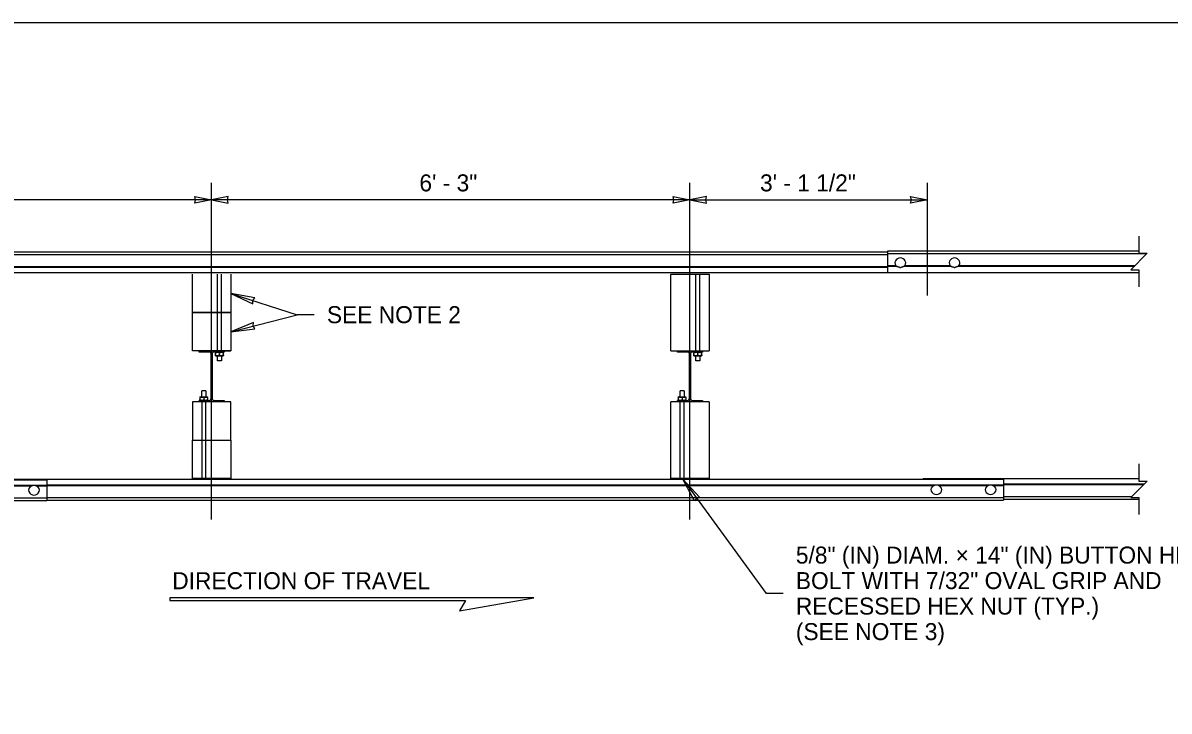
# Model space of a CAD drawing. Extents: x 99862 to 103680, y 99470 to 102076.
# Drawn here: x 101011 to 102089, y 101428 to 102076 of the extents above; entities that cross this region are included whole.
import ezdxf

# ---------------------------------------------------------------- set-up
doc = ezdxf.new("R2010")
doc.units = 0
for name, color, linetype in [('Level 1', 7, 'Continuous'), ('Level 10', 7, 'Continuous'), ('Level 14', 7, 'Continuous'), ('Level 15', 7, 'Continuous'), ('Level 2', 7, 'Continuous'), ('Level 20', 7, 'Continuous'), ('Level 27', 7, 'Continuous'), ('Level 4', 7, 'Continuous'), ('Level 7', 7, 'Continuous')]:
    doc.layers.add(name, color=color, linetype=linetype)

msp = doc.modelspace()

# ---------------------------------------------------------------- linework, layer by layer
at = {"layer": 'Level 1'}
msp.add_lwpolyline([(99862, 99999.5), (103151, 99999.5), (103151, 102075.5), (99862, 102075.5)], close=True, dxfattribs=at)
at = {"layer": 'Level 10'}
for p, q in [((101824.3, 101857.4), (100924.3, 101857.4)), ((101824.3, 101845.5), (100924.3, 101845.5)), ((100989.7, 101846.4), (101824.3, 101846.4)), ((100133.2, 101640.6), (101033.2, 101640.6)), ((101018.7, 101639.7), (100972.7, 101639.7)), ((101033.2, 101639.7), (101023.7, 101639.7)), ((101933.2, 101641.8), (102065.8, 101641.8)), ((102064.9, 101640.9), (101933.2, 101640.9)), ((100133.2, 101628.7), (101033.2, 101628.7)), ((101933.2, 101629.9), (102053.9, 101629.9))]:
    msp.add_line(p, q, dxfattribs=at)
msp.add_open_spline([(101857.7, 101646.9), (101857.7, 101646.5), (101857.7, 101646.1)], degree=2, dxfattribs=at)
at = {"layer": 'Level 14'}
for p, q in [((101188.3, 101608.2), (101188.3, 101925)), ((101638.3, 101608.2), (101638.3, 101925)), ((101861.8, 101819), (101861.8, 101925))]:
    msp.add_line(p, q, dxfattribs=at)
at = {"layer": 'Level 15'}
for p, q in [((101188.3, 101909), (100738.4, 101909)), ((101638.3, 101909), (101188.3, 101909)), ((101638.3, 101909), (101861.8, 101909)), ((101206.3, 101821), (101268.8, 101801)), ((101206.3, 101785), (101268.8, 101801)), ((101284.8, 101801), (101268.8, 101801)), ((101631.6, 101646.1), (101710, 101538.8)), ((101726, 101538.8), (101710, 101538.8))]:
    msp.add_line(p, q, dxfattribs=at)
for points in [[(101188.3, 101909), (101172.5, 101905.9), (101173.3, 101909), (101172.5, 101912.1)], [(101188.3, 101909), (101204, 101905.9), (101203.3, 101909), (101204, 101912.1)], [(101638.3, 101909), (101622.5, 101905.9), (101623.3, 101909), (101622.5, 101912.1)], [(101638.3, 101909), (101654, 101905.9), (101653.3, 101909), (101654, 101912.1)], [(101861.8, 101909), (101846, 101905.9), (101846.8, 101909), (101846, 101912.1)], [(101206.3, 101821), (101227.1, 101811.2), (101227, 101814.4), (101228.9, 101816.9)], [(101206.3, 101785), (101229.1, 101787.8), (101227.4, 101790.4), (101227.6, 101793.6)], [(101631.6, 101646.1), (101647.4, 101629.4), (101644.4, 101628.5), (101642.6, 101625.9)]]:
    msp.add_lwpolyline(points, close=True, dxfattribs=at)
for points in [[(102060.8, 101874.8), (102060.8, 101858.8), (102068.6, 101858.8), (102053.1, 101843.3), (102060.8, 101843.3), (102060.8, 101827.3)], [(102060.8, 101660.5), (102060.8, 101644.5), (102068.6, 101644.5), (102053.1, 101629.1), (102060.8, 101629.1), (102060.8, 101613.1)]]:
    msp.add_lwpolyline(points, dxfattribs=at)
at = {"layer": 'Level 2'}
for p, q in [((101170.3, 101803), (101170.3, 101839)), ((101206.3, 101839), (101206.3, 101803)), ((101620.3, 101767), (101620.3, 101839)), ((101620.3, 101839), (101656.3, 101839)), ((101656.3, 101839), (101656.3, 101767)), ((101170.3, 101767), (101170.3, 101803)), ((101170.3, 101803), (101206.3, 101803)), ((101206.3, 101803), (101170.3, 101803)), ((101206.3, 101803), (101206.3, 101767)), ((101206.3, 101767), (101170.3, 101767)), ((101201, 101767), (101206.3, 101767)), ((101620.3, 101767), (101625.5, 101767)), ((101625.5, 101767), (101651, 101767)), ((101651, 101767), (101656.3, 101767)), ((101170.3, 101719), (101170.3, 101683)), ((101206.3, 101719), (101170.3, 101719)), ((101206.3, 101683), (101206.3, 101719)), ((101620.3, 101647), (101620.3, 101719)), ((101625.5, 101719), (101620.3, 101719)), ((101651, 101719), (101625.5, 101719)), ((101656.3, 101719), (101651, 101719)), ((101656.3, 101719), (101656.3, 101647)), ((101170.3, 101683), (101206.3, 101683)), ((101170.3, 101647), (101170.3, 101683)), ((101206.3, 101683), (101206.3, 101647)), ((101206.3, 101647), (101170.3, 101647)), ((101656.3, 101647), (101620.3, 101647))]:
    msp.add_line(p, q, dxfattribs=at)
at = {"layer": 'Level 20'}
msp.add_lwpolyline([(101149, 101532.2), (101427.3, 101532.2), (101421.6, 101522.3), (101491.6, 101534.6), (101149, 101534.6)], close=True, dxfattribs=at)
at = {"layer": 'Level 27'}
for p, q in [((101824.3, 101859.8), (100924.3, 101859.8)), ((102060.8, 101860.7), (101824.3, 101860.7)), ((101824.3, 101860.7), (101824.3, 101840.4)), ((102068, 101858.3), (101824.3, 101858.3)), ((102060.8, 101840.4), (100924.3, 101840.4)), ((101824.3, 101847.3), (101832.2, 101847.3)), ((101833.4, 101846.4), (101824.3, 101846.4)), ((101884.4, 101846.4), (101839.2, 101846.4)), ((101840.3, 101847.3), (101883.2, 101847.3)), ((102056.1, 101846.4), (101890.2, 101846.4)), ((101891.3, 101847.3), (102057.1, 101847.3)), ((100133.2, 101645.6), (101033.2, 101645.6)), ((100958.2, 101646.1), (101933.2, 101646.1)), ((101857.7, 101646.9), (102060.7, 101646.9)), ((101033.2, 101641), (101933.2, 101641)), ((101867.7, 101640.1), (101033.2, 101640.1)), ((101918.7, 101640.1), (101872.7, 101640.1)), ((101933.2, 101640.1), (101923.7, 101640.1)), ((99896.7, 101626.2), (101033.2, 101626.2)), ((101033.2, 101629.1), (101933.2, 101629.1)), ((101033.2, 101626.6), (101933.2, 101626.6)), ((101933.2, 101627.5), (102060.7, 101627.5))]:
    msp.add_line(p, q, dxfattribs=at)
for points in [[(101033.2, 101645.6), (101033.2, 101643.1), (101033.2, 101640.6), (101033.2, 101640.1), (101033.2, 101639.7), (101033.2, 101634.2), (101033.2, 101628.7), (101033.2, 101626.2), (101033.2, 101626.2)], [(101933.2, 101646.1), (101933.2, 101643.5), (101933.2, 101641), (101933.2, 101640.5), (101933.2, 101640.1), (101933.2, 101634.6), (101933.2, 101629.1), (101933.2, 101626.6), (101933.2, 101626.6)]]:
    msp.add_open_spline(points, degree=4, dxfattribs=at)
at = {"layer": 'Level 4'}
for p, q in [((101176.5, 101765.7), (101176.5, 101767)), ((101176.5, 101767), (101200.1, 101767)), ((101186.3, 101765.7), (101176.5, 101765.7)), ((101187.8, 101742.7), (101187.8, 101764.2)), ((101188.8, 101764.2), (101188.8, 101742.7)), ((101200.1, 101765.7), (101190.3, 101765.7)), ((101200.1, 101767), (101200.1, 101765.7)), ((101626.5, 101765.7), (101626.5, 101767)), ((101626.5, 101767), (101650.1, 101767)), ((101636.3, 101765.7), (101626.5, 101765.7)), ((101637.8, 101742.7), (101637.8, 101764.2)), ((101638.8, 101764.2), (101638.8, 101742.7)), ((101650.1, 101765.7), (101640.3, 101765.7)), ((101650.1, 101767), (101650.1, 101765.7)), ((101187.8, 101721.8), (101187.8, 101743.1)), ((101188.8, 101743.1), (101188.8, 101721.8)), ((101637.8, 101721.8), (101637.8, 101743.1)), ((101638.8, 101743.1), (101638.8, 101721.8)), ((101176.5, 101719), (101176.5, 101720.3)), ((101176.5, 101720.3), (101186.3, 101720.3)), ((101200.1, 101719), (101176.5, 101719)), ((101190.3, 101720.3), (101200.1, 101720.3)), ((101200.1, 101720.3), (101200.1, 101719)), ((101626.5, 101719), (101626.5, 101720.3)), ((101626.5, 101720.3), (101636.3, 101720.3)), ((101650.1, 101719), (101626.5, 101719)), ((101640.3, 101720.3), (101650.1, 101720.3)), ((101650.1, 101720.3), (101650.1, 101719))]:
    msp.add_line(p, q, dxfattribs=at)
for centre, start, end in [((101186.3, 101764.2), 0, 90), ((101190.3, 101764.2), 90, 180), ((101636.3, 101764.2), 0, 90), ((101640.3, 101764.2), 90, 180), ((101186.3, 101721.8), 270, 0), ((101190.3, 101721.8), 180, 270), ((101636.3, 101721.8), 270, 0), ((101640.3, 101721.8), 180, 270)]:
    msp.add_arc(centre, 1.5, start, end, dxfattribs=at)
at = {"layer": 'Level 7'}
for p, q in [((101193.8, 101767), (101193.8, 101839)), ((101197.5, 101767), (101197.5, 101839)), ((101643.8, 101767), (101643.8, 101839)), ((101647.5, 101767), (101647.5, 101839)), ((101192.1, 101765.6), (101192.1, 101765.7)), ((101192.1, 101763.3), (101192.1, 101764.9)), ((101195.7, 101763.3), (101195.7, 101764.9)), ((101199.3, 101765.7), (101199.4, 101765.6)), ((101199.4, 101763.3), (101199.4, 101764.9)), ((101642.1, 101765.6), (101642.1, 101765.7)), ((101642.1, 101763.3), (101642.1, 101764.9)), ((101645.7, 101763.3), (101645.7, 101764.9)), ((101649.3, 101765.7), (101649.4, 101765.6)), ((101649.4, 101763.3), (101649.4, 101764.9)), ((101192.1, 101762.4), (101192.1, 101762.5)), ((101192.1, 101762.4), (101197.4, 101762.4)), ((101193.8, 101757.6), (101193.8, 101762.4)), ((101197.6, 101757.6), (101193.8, 101757.6)), ((101197.4, 101762.4), (101199.3, 101762.4)), ((101197.6, 101762.4), (101197.6, 101757.6)), ((101199.4, 101762.5), (101199.3, 101762.4)), ((101642.1, 101762.4), (101642.1, 101762.5)), ((101642.1, 101762.4), (101647.4, 101762.4)), ((101643.8, 101757.6), (101643.8, 101762.4)), ((101647.6, 101757.6), (101643.8, 101757.6)), ((101647.4, 101762.4), (101649.3, 101762.4)), ((101647.6, 101762.4), (101647.6, 101757.6)), ((101649.4, 101762.5), (101649.3, 101762.4)), ((101177.3, 101723.5), (101177.4, 101723.6)), ((101177.3, 101722.8), (101177.3, 101721.2)), ((101177.4, 101723.6), (101184.6, 101723.6)), ((101182.8, 101729.3), (101179.1, 101729.3)), ((101179.1, 101723.6), (101179.1, 101729.3)), ((101181, 101722.8), (101181, 101721.2)), ((101182.8, 101729.3), (101182.8, 101723.6)), ((101184.6, 101723.6), (101184.6, 101723.5)), ((101184.6, 101722.8), (101184.6, 101721.2)), ((101627.3, 101723.5), (101627.4, 101723.6)), ((101627.3, 101722.8), (101627.3, 101721.2)), ((101627.4, 101723.6), (101634.6, 101723.6)), ((101632.8, 101729.3), (101629.1, 101729.3)), ((101629.1, 101723.6), (101629.1, 101729.3)), ((101631, 101722.8), (101631, 101721.2)), ((101632.8, 101729.3), (101632.8, 101723.6)), ((101634.6, 101723.6), (101634.6, 101723.5)), ((101634.6, 101722.8), (101634.6, 101721.2)), ((101177.4, 101720.3), (101177.3, 101720.4)), ((101179.3, 101646.1), (101179.3, 101718.8)), ((101183, 101646.1), (101183, 101718.8)), ((101184.6, 101720.4), (101184.6, 101720.3)), ((101627.4, 101720.3), (101627.3, 101720.4)), ((101629.3, 101646.1), (101629.3, 101718.8)), ((101633, 101646.1), (101633, 101718.8)), ((101634.6, 101720.4), (101634.6, 101720.3))]:
    msp.add_line(p, q, dxfattribs=at)
for centre, start, end in [((101836.3, 101849.1), 27.8334, 152.1666), ((101887.3, 101849.1), 27.8334, 152.1666), ((101021.2, 101636.5), 202.4988, 337.5012), ((101870.2, 101637), 202.4988, 337.5012), ((101921.2, 101637), 202.4988, 337.5012)]:
    msp.add_arc(centre, 5.27, start, end, dxfattribs=at)
for centre, major_axis, ratio, start_param, end_param in [((101836.3, 101849.8), (5.09, 0), 0.829603, 2.728747, 4.097738), ((101836.3, 101849.8), (5.09, 0), 0.829603, 5.32704, 6.69603), ((101887.3, 101849.8), (5.09, 0), 0.829603, 2.728747, 4.097738), ((101887.3, 101849.8), (5.09, 0), 0.829603, 5.32704, 6.69603), ((101836.3, 101849.6), (4.23, 0), 0.984494, 4.617198, 4.80758), ((101887.3, 101849.6), (4.23, 0), 0.984494, 4.617198, 4.80758), ((101021.2, 101635.9), (-5.15, 0), 0.829603, 5.211482, 6.615288), ((101021.2, 101635.9), (5.15, 0), 0.829604, 1.071482, 2.070111), ((101021.2, 101635.9), (-5.15, 0), 0.829603, 2.80949, 4.213296), ((101870.2, 101636.3), (-5.15, 0), 0.829603, 5.211482, 6.615288), ((101870.2, 101636.3), (5.15, 0), 0.829604, 1.071482, 2.070111), ((101870.2, 101636.3), (-5.15, 0), 0.829603, 2.80949, 4.213296), ((101921.2, 101636.3), (-5.15, 0), 0.829603, 5.211482, 6.615288), ((101921.2, 101636.3), (5.15, 0), 0.829604, 1.071482, 2.070111), ((101921.2, 101636.3), (-5.15, 0), 0.829603, 2.80949, 4.213296)]:
    msp.add_ellipse(centre, major_axis=major_axis, ratio=ratio, start_param=start_param, end_param=end_param, dxfattribs=at)
for points, degree in [([(101835.9, 101845.5), (101835.4, 101845.5), (101834.9, 101845.7), (101834.4, 101845.8), (101834, 101846), (101833.7, 101846.2), (101833.3, 101846.4)], 3), ([(101839.2, 101846.4), (101838.7, 101846.1), (101838.2, 101845.9), (101837.7, 101845.7), (101837.4, 101845.6), (101837, 101845.5), (101836.7, 101845.5)], 3), ([(101886.9, 101845.5), (101886.4, 101845.5), (101885.9, 101845.7), (101885.4, 101845.8), (101885, 101846), (101884.7, 101846.2), (101884.3, 101846.4)], 3), ([(101890.2, 101846.4), (101889.7, 101846.1), (101889.2, 101845.9), (101888.7, 101845.7), (101888.4, 101845.6), (101888, 101845.5), (101887.7, 101845.5)], 3), ([(101192.1, 101764.9), (101192.6, 101765.3), (101193.2, 101765.6), (101194.5, 101765.7), (101195.2, 101765.3), (101195.7, 101764.9)], 3), ([(101192.1, 101765.6), (101192.1, 101765.7), (101192.1, 101765.3), (101192.1, 101764.9)], 2), ([(101195.7, 101764.9), (101196.3, 101765.3), (101196.9, 101765.6), (101198.2, 101765.7), (101198.8, 101765.3), (101199.4, 101764.9)], 3), ([(101199.4, 101764.9), (101199.4, 101765.3), (101199.4, 101765.6), (101199.4, 101765.6), (101199.4, 101765.6), (101199.4, 101765.6)], 3), ([(101642.1, 101764.9), (101642.6, 101765.3), (101643.2, 101765.6), (101644.5, 101765.7), (101645.2, 101765.3), (101645.7, 101764.9)], 3), ([(101642.1, 101765.6), (101642.1, 101765.7), (101642.1, 101765.3), (101642.1, 101764.9)], 2), ([(101645.7, 101764.9), (101646.3, 101765.3), (101646.9, 101765.6), (101648.2, 101765.7), (101648.8, 101765.3), (101649.4, 101764.9)], 3), ([(101649.4, 101764.9), (101649.4, 101765.3), (101649.4, 101765.6), (101649.4, 101765.6), (101649.4, 101765.6), (101649.4, 101765.6)], 3), ([(101192.1, 101762.5), (101192.1, 101762.5), (101192.1, 101762.9), (101192.1, 101763.3)], 2), ([(101192.1, 101763.3), (101192.6, 101762.9), (101193.2, 101762.5), (101194.5, 101762.5), (101195.2, 101762.9), (101195.7, 101763.3)], 3), ([(101195.7, 101763.3), (101196.3, 101762.9), (101196.9, 101762.5), (101198.2, 101762.5), (101198.8, 101762.9), (101199.4, 101763.3)], 3), ([(101199.4, 101763.3), (101199.4, 101762.9), (101199.4, 101762.5), (101199.4, 101762.5), (101199.4, 101762.5), (101199.4, 101762.5)], 3), ([(101642.1, 101762.5), (101642.1, 101762.5), (101642.1, 101762.9), (101642.1, 101763.3)], 2), ([(101642.1, 101763.3), (101642.6, 101762.9), (101643.2, 101762.5), (101644.5, 101762.5), (101645.2, 101762.9), (101645.7, 101763.3)], 3), ([(101645.7, 101763.3), (101646.3, 101762.9), (101646.9, 101762.5), (101648.2, 101762.5), (101648.8, 101762.9), (101649.4, 101763.3)], 3), ([(101649.4, 101763.3), (101649.4, 101762.9), (101649.4, 101762.5), (101649.4, 101762.5), (101649.4, 101762.5), (101649.4, 101762.5)], 3), ([(101177.3, 101723.5), (101177.3, 101723.5), (101177.3, 101723.2), (101177.3, 101722.8)], 2), ([(101177.3, 101722.8), (101177.9, 101723.2), (101178.5, 101723.5), (101179.8, 101723.5), (101180.4, 101723.2), (101181, 101722.8)], 3), ([(101177.3, 101720.4), (101177.3, 101720.4), (101177.3, 101720.8), (101177.3, 101721.2)], 2), ([(101177.3, 101721.2), (101177.9, 101720.8), (101178.5, 101720.4), (101179.8, 101720.4), (101180.4, 101720.8), (101181, 101721.2)], 3), ([(101181, 101722.8), (101181.5, 101723.2), (101182.1, 101723.5), (101183.4, 101723.5), (101184.1, 101723.2), (101184.6, 101722.8)], 3), ([(101181, 101721.2), (101181.5, 101720.8), (101182.1, 101720.4), (101183.4, 101720.4), (101184.1, 101720.8), (101184.6, 101721.2)], 3), ([(101184.6, 101722.8), (101184.6, 101723.2), (101184.6, 101723.5), (101184.6, 101723.5), (101184.6, 101723.5), (101184.6, 101723.5)], 3), ([(101184.6, 101721.2), (101184.6, 101720.8), (101184.6, 101720.4), (101184.6, 101720.4), (101184.6, 101720.4), (101184.6, 101720.4)], 3), ([(101627.3, 101723.5), (101627.3, 101723.5), (101627.3, 101723.2), (101627.3, 101722.8)], 2), ([(101627.3, 101722.8), (101627.9, 101723.2), (101628.5, 101723.5), (101629.8, 101723.5), (101630.4, 101723.2), (101631, 101722.8)], 3), ([(101627.3, 101720.4), (101627.3, 101720.4), (101627.3, 101720.8), (101627.3, 101721.2)], 2), ([(101627.3, 101721.2), (101627.9, 101720.8), (101628.5, 101720.4), (101629.8, 101720.4), (101630.4, 101720.8), (101631, 101721.2)], 3), ([(101631, 101722.8), (101631.5, 101723.2), (101632.1, 101723.5), (101633.4, 101723.5), (101634.1, 101723.2), (101634.6, 101722.8)], 3), ([(101631, 101721.2), (101631.5, 101720.8), (101632.1, 101720.4), (101633.4, 101720.4), (101634.1, 101720.8), (101634.6, 101721.2)], 3), ([(101634.6, 101722.8), (101634.6, 101723.2), (101634.6, 101723.5), (101634.6, 101723.5), (101634.6, 101723.5), (101634.6, 101723.5)], 3), ([(101634.6, 101721.2), (101634.6, 101720.8), (101634.6, 101720.4), (101634.6, 101720.4), (101634.6, 101720.4), (101634.6, 101720.4)], 3)]:
    msp.add_open_spline(points, degree=degree, dxfattribs=at)

# ---------------------------------------------------------------- texts
at = {"layer": 'Level 20'}
for s, p in [('6\' - 3"', (101383.8, 101917)), ('3\' - 1 1/2"', (101704.3, 101917)), ('5/8" (IN) DIAM. × 14" (IN) BUTTON HEAD', (101738, 101566.8)), ('BOLT WITH 7/32" OVAL GRIP AND', (101738, 101542.8)), ('DIRECTION OF TRAVEL', (101151.3, 101542.7)), ('RECESSED HEX NUT (TYP.)', (101738, 101518.8)), ('(SEE NOTE 3)', (101738, 101494.8))]:
    msp.add_text(s, height=16, dxfattribs=at).set_placement(p)
msp.add_text('SEE NOTE 2', height=16, rotation=360, dxfattribs=at).set_placement((101296.8, 101793))

doc.saveas('drawing.dxf')
